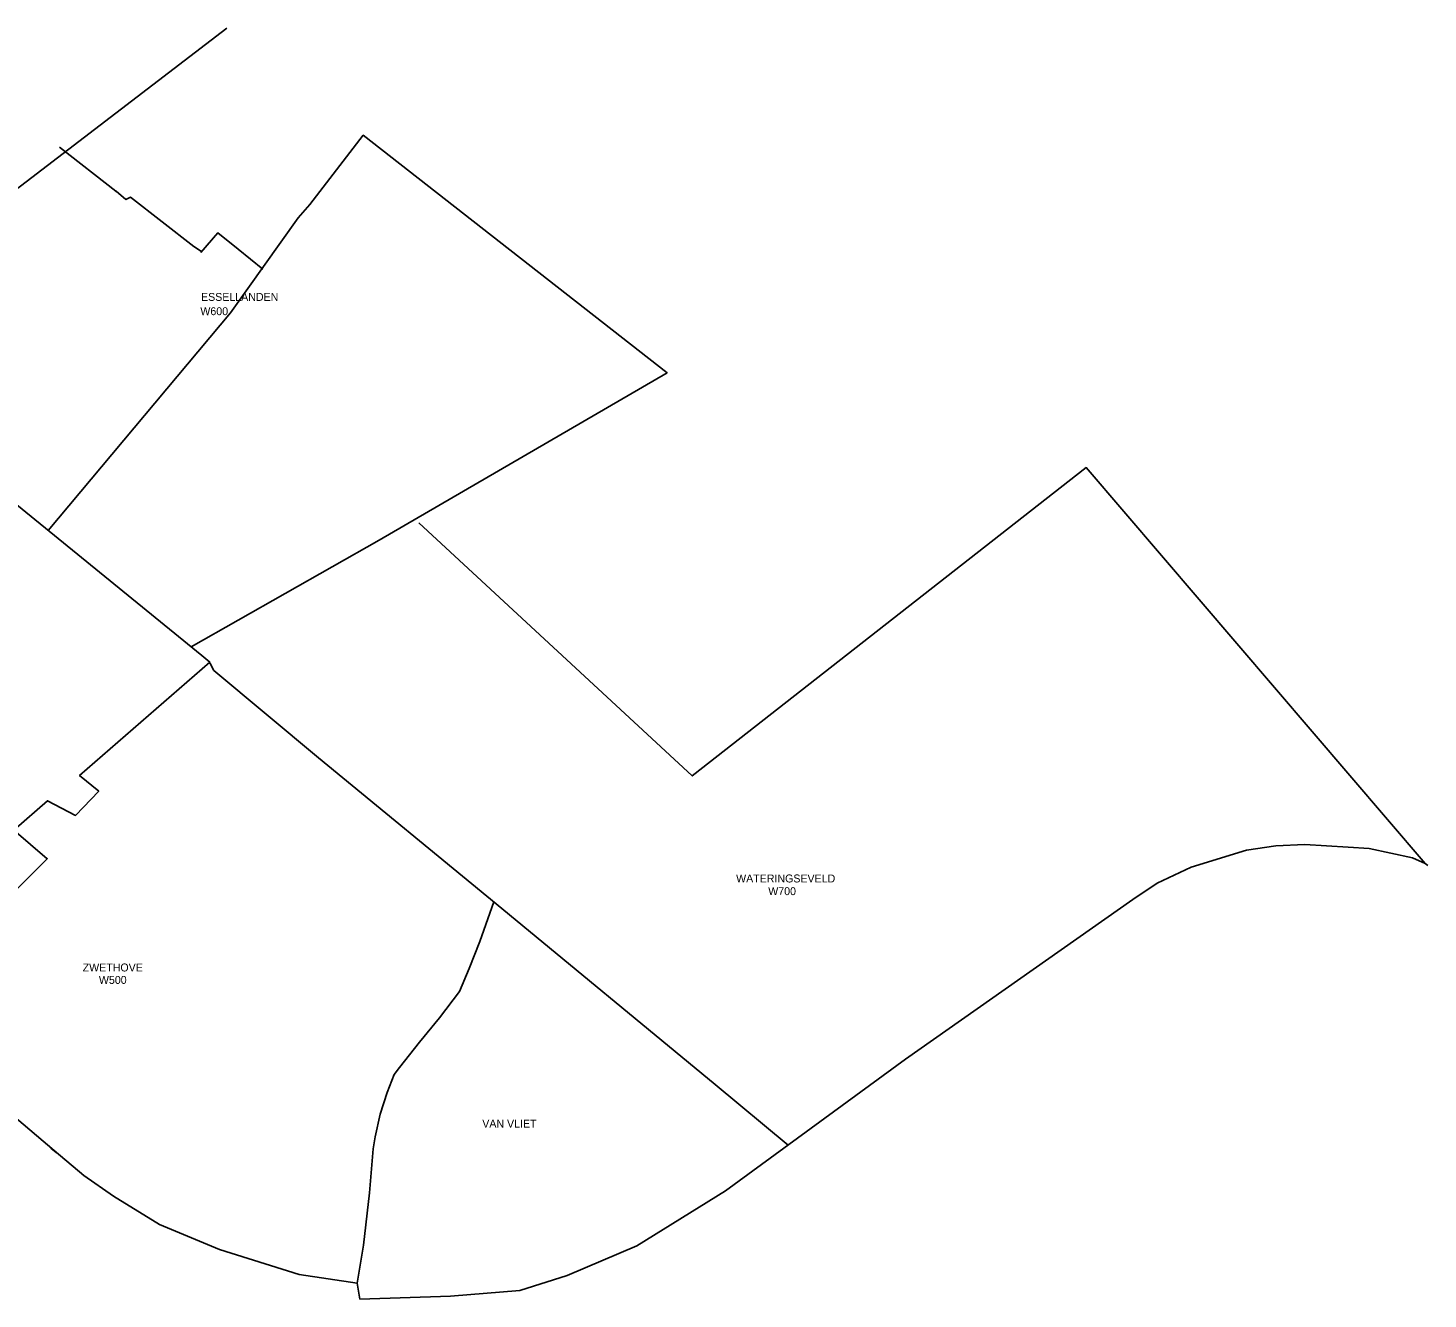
# Model space of a CAD drawing. Extents: x 69068 to 80855, y 440023 to 451362.
# Drawn here: x 79268 to 80855, y 447408 to 448849 of the extents above; entities that cross this region are included whole.
import ezdxf

# ---------------------------------------------------------------- set-up
doc = ezdxf.new("R2010")
doc.units = 0
for name, color, linetype in [('Bemalingsgebiedsgrens', 7, 'Continuous'), ('Bemalingsgebiedsnummer', 7, 'Continuous'), ('RIO_Leidingen', 7, 'Continuous')]:
    doc.layers.add(name, color=color, linetype=linetype)

msp = doc.modelspace()

# ---------------------------------------------------------------- linework, layer by layer
at = {"layer": 'Bemalingsgebiedsgrens'}
for p, q in [((79453.2, 448147.5), (79666.4, 448268.2)), ((80649.5, 447916.8), (80682.7, 447921.8)), ((80682.7, 447921.8), (80715.8, 447923.3)), ((80715.8, 447923.3), (80764.8, 447920.4)), ((80764.8, 447920.4), (80788.6, 447918.7)), ((80586.9, 447897.8), (80649.5, 447916.8)), ((80788.6, 447918.7), (80837.9, 447908.2)), ((80837.9, 447908.2), (80852, 447901.7)), ((80548.4, 447879.4), (80586.9, 447897.8)), ((80852, 447901.7), (80855.3, 447899.4)), ((80520.9, 447861), (80548.4, 447879.4)), ((80263.1, 447679.9), (80520.9, 447861)), ((80058.8, 447530.9), (80263.1, 447679.9)), ((79294.2, 447579.2), (79300.1, 447574.3)), ((79297.7, 447576.4), (79331.4, 447548.2)), ((79331.4, 447548.2), (79365.1, 447524.5)), ((79365.1, 447524.5), (79417.1, 447492.6)), ((79958.4, 447468.2), (80058.8, 447530.9)), ((79417.1, 447492.6), (79485.4, 447464.3)), ((79485.4, 447464.3), (79575.7, 447436)), ((79879.3, 447434.9), (79958.4, 447468.2)), ((79575.7, 447436), (79641.3, 447426)), ((79825.7, 447417.7), (79879.3, 447434.9)), ((79641.3, 447426), (79644.5, 447408.1)), ((79644.5, 447408.1), (79747.2, 447411.5)), ((79747.2, 447411.5), (79825.7, 447417.7))]:
    msp.add_line(p, q, dxfattribs=at)
for points in [[(79031.1, 448486.9), (79181.7, 448610.2), (79493.5, 448848.8)], [(79291.2, 448279.2), (79497.7, 448526), (79574.4, 448633.5), (79587.6, 448648.8), (79648.2, 448727.2), (79992.8, 448458), (79666.4, 448268.2)], [(79304, 448713.9), (79367.8, 448663.9), (79367.9, 448663.5), (79368.1, 448663.7), (79379.2, 448654.6), (79384.6, 448657.1), (79456.1, 448601.1), (79464.9, 448595.4), (79464.9, 448595.4)], [(79464.2, 448594.4), (79483.4, 448616.5), (79506.5, 448598.2), (79534.5, 448575.4)], [(80852, 447901.7), (80468, 448350.6), (80021.2, 448001.1), (79711.1, 448287.9)], [(79046.2, 448172.2), (79180.3, 448233.2), (79245.3, 448316.8), (79465.2, 448137.5)], [(79465.2, 448137.5), (79474.2, 448130), (79326.7, 448001.5), (79348.4, 447983.6), (79322.2, 447956.2), (79290.4, 447972.9), (79252.2, 447939.7), (79290.1, 447907.1), (79253.8, 447870.8), (79212.7, 447906.1), (79059.3, 447778.7), (79297.7, 447576.4)], [(79474.2, 448129.3), (79478.7, 448120.7), (79597.6, 448021.7), (79799, 447856.1), (80047.4, 447651.2), (80130.1, 447582.5)], [(79796.3, 447858.4), (79780.6, 447813.4), (79768.5, 447782.9), (79757.5, 447756.8), (79734.9, 447726.8), (79711.9, 447699.1), (79689.2, 447670.6), (79683.4, 447662.7), (79675.5, 447642.3), (79667.4, 447617.8), (79661.6, 447592), (79659.6, 447578.5), (79655.4, 447528.3), (79648.4, 447469.1), (79641.3, 447426)]]:
    msp.add_lwpolyline(points, dxfattribs=at)

# ---------------------------------------------------------------- texts
at = {"layer": 'Bemalingsgebiedsnummer'}
for s, p in [('W600', (79463.6, 448523.3)), ('W700', (80107.4, 447865.9)), ('W500', (79348.6, 447765.3))]:
    msp.add_text(s, height=9, dxfattribs=at).set_placement(p)
at = {"layer": 'RIO_Leidingen'}
for s, p in [('ESSELLANDEN', (79464.4, 448539.5)), ('WATERINGSEVELD', (80071, 447880.3)), ('ZWETHOVE', (79330.2, 447779.4)), ('VAN VLIET', (79783.2, 447602.4))]:
    msp.add_text(s, height=9, dxfattribs=at).set_placement(p)

doc.saveas('drawing.dxf')
